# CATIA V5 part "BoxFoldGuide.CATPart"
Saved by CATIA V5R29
Part number: BoxFoldGuide
Bounding box of the stored display mesh (mm): x -50 to 50, y -1500 to 0, z 611 to 1381
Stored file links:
  C:\Users\Administrator\Desktop\프로젝트\Boxfold\BoxFoldGuide.CATPart
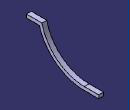
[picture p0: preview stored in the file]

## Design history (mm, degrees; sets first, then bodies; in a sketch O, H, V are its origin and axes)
Body1 (main body)
  DatumCurve1 to DatumCurve5
  Sketch1 on yz-plane, origin (0, 0, 0), H (0, 1, 0), V (0, 0, 1)
    point P2 (-300, 681)
    arc A1 centre (-300, 1581) radius 900 from (-1177.4964, 1381) to (-300, 681) ccw
    point P5 (-300, 681)
    line L1 (-1177.4964, 1381) -> (-1500, 1381)
    line L2 (-300, 681) -> (0, 681)
    line L3 (-1231.6652, 1311) -> (-1500, 1311)
    arc A2 centre (-300, 1581) radius 970 from (-1231.6652, 1311) to (-300, 611) ccw
    point P9 (-300, 611)
    line L4 (-300, 611) -> (0, 611)
    line L5 (0, 611) -> (0, 681)
    line L6 (-1500, 1311) -> (-1500, 1381)
    reference projected line E1 (200, 611) -> (400, 611) from edge of DatumCurve4
    radius A1 = 900
    distance L1 L3 = 70
    distance L2 L4 = 70
    distance L5 L6 = 1500
    distance L5 P9 = 300
    distance L3 L4 = 700
    coincidence: P5 P2, L4 E1, L5 V
    horizontal: L1 H, L2 H, L4 H, L3 H
    tangency: A1 L2, L4 A2
    vertical: L5 V, L6 V
    concentricity: A2 A1
  Pad1: profile Sketch1, direction (1, 0, 0), length 50, mirrored extent
  DatumCurve6
  Sketch2 on face of Pad1 from Sketch1.L3, origin (-27.7615, -1390.7753, 1311), H (1, 0, 0), V (0, -1, 0)
    point P1 (-0.3843, 0.4747)
    reference projected circle E1 centre (-0.3843, 0.4747) radius 3.3 from edge of DatumCurve5
    concentricity: E1 P1
  Hole1: placed by Sketch2, at (-28.1458, -1391.25, 1311) direction (0, 0, 1), diameter 4.917, depth 10, V-bottom angle 120, threaded "M6", thread diameter 6, thread depth 10, pitch 1
  DatumCurve7
  Sketch3 on face of Pad1 from Sketch1.L3, origin (27.744, -1391.1157, 1311), H (1, 0, 0), V (0, -1, 0)
    point P1 (0.4018, 0.1343)
    reference projected circle E1 centre (0.4018, 0.1343) radius 3.3 from edge of DatumCurve6
    concentricity: E1 P1
  Hole2: placed by Sketch3, at (28.1458, -1391.25, 1311) direction (0, 0, 1), diameter 4.917, depth 10, V-bottom angle 120, threaded "M6", thread diameter 6, thread depth 10, pitch 1
  DatumCurve8
  Sketch4 on face of Pad1 from Sketch1.L3, origin (0.5823, -1342.6396, 1311), H (1, 0, 0), V (0, -1, 0)
    point P1 (-0.5823, -0.1396)
    reference projected circle E1 centre (-0.5823, -0.1396) radius 3.3 from edge of DatumCurve7
    concentricity: E1 P1
  Hole3: placed by Sketch4, at (0, -1342.5, 1311) direction (0, 0, 1), diameter 4.917, depth 10, V-bottom angle 120, threaded "M6", thread diameter 6, thread depth 10, pitch 1
  Sketch5 on face of Pad1 from Sketch1.L3, origin (28.7826, -1376.1973, 1311), H (1, 0, 0), V (0, -1, 0)
    point P1 (-0.6368, 0.0527)
    reference projected circle E1 centre (-0.6368, 0.0527) radius 3.3 from edge of DatumCurve8
    concentricity: E1 P1
  Hole4: placed by Sketch5, at (28.1458, -1376.25, 1311) direction (0, 0, 1), diameter 4.917, depth 10, V-bottom angle 120, threaded "M6", thread diameter 6, thread depth 10, pitch 1
  Sketch6 on face of Pad1 from Sketch1.L3, origin (0, 0, 1311), H (0, 1, 0), V (1, 0, 0)
    point P1 (-1326.923, 0)
    point P2 (-1375.5234, -27.4482)
    coincidence: P1 H
  DatumCurve9 to DatumCurve11
  Sketch7 on face of Pad1 from Sketch1.L4, origin (0, 0, 611), H (0, 1, 0), V (1, 0, 0)
    point P1 (-166.25, -28.1458)
    point P2 (-117.5, 0)
    reference projected circle E1 centre (-117.5, 0) radius 3.3 from edge of DatumCurve9
    reference projected circle E2 centre (-166.25, -28.1458) radius 3.3 from edge of DatumCurve11
    concentricity: P2 E1, P1 E2
  DatumCurve12
  UserPattern1: of Hole4, copies 3, at the points of Sketch6
  Sketch8 on face of Pad1 from Sketch1.L4, origin (28.7766, -166.2946, 611), H (1, 0, 0), V (0, -1, 0)
    point P1 (-0.6308, -0.0446)
    reference projected circle E1 centre (-0.6308, -0.0446) radius 3.3 from edge of DatumCurve12
    concentricity: E1 P1
  Hole5: placed by Sketch8, at (28.1458, -166.25, 611) direction (0, 0, 1), diameter 4.917, depth 10, V-bottom angle 120, threaded "M6", thread diameter 6, thread depth 10, pitch 1
  UserPattern2: of Hole5, copies 3, at the points of Sketch7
